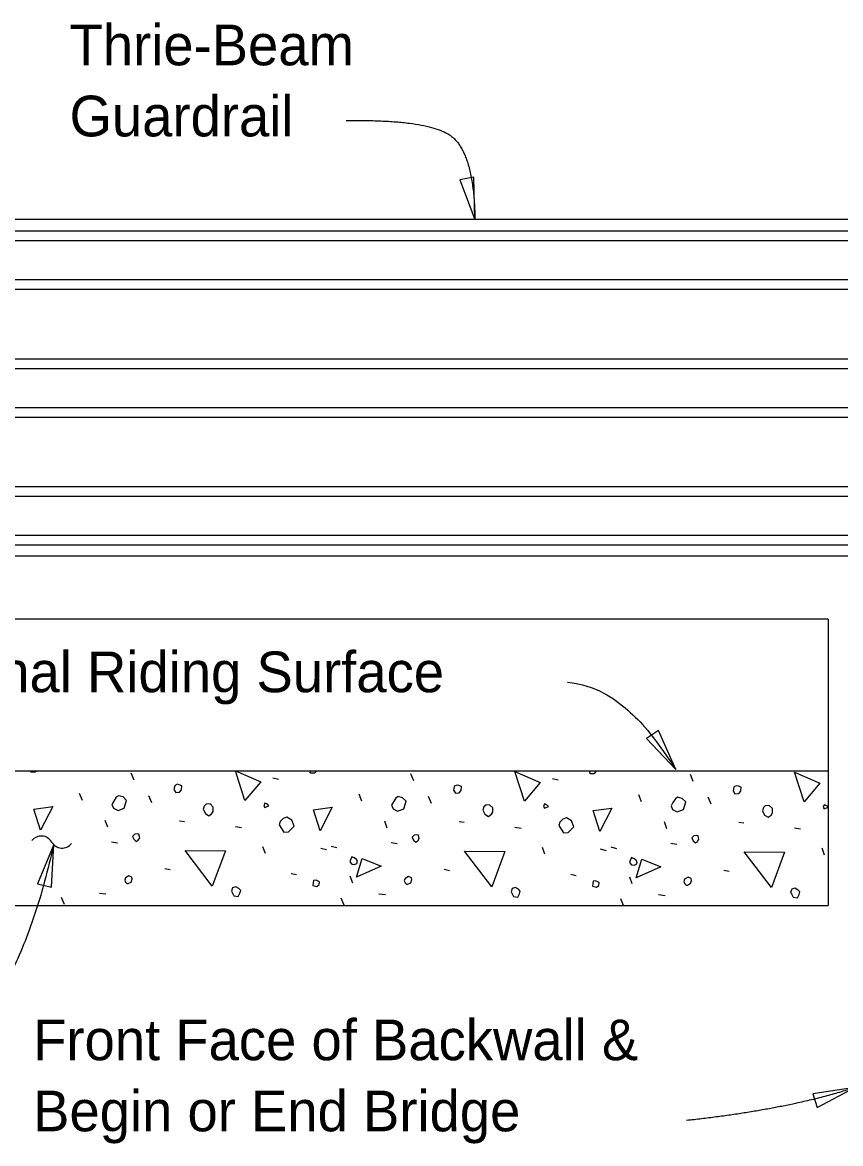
# Model space of a CAD drawing. Extents: x 21587 to 21656.3, y 56114 to 56157.2.
# Drawn here: x 21589.85 to 21593.9, y 56132.2 to 56137.76 of the extents above; entities that cross this region are included whole.
import ezdxf

# ---------------------------------------------------------------- set-up
doc = ezdxf.new("R2010")
doc.units = 0
for name, color, linetype in [('AdhocPoint_dp', 7, 'Continuous'), ('Border', 7, 'Continuous'), ('PlotBorder_dp', 7, 'Continuous'), ('SheetBorder_dp', 7, 'Continuous'), ('TextMisc', 7, 'Continuous')]:
    doc.layers.add(name, color=color, linetype=linetype)

msp = doc.modelspace()

# ---------------------------------------------------------------- linework, layer by layer
at = {"layer": 'AdhocPoint_dp'}
for p, q in [((21593.837, 56134.8009), (21587.6633, 56134.8009)), ((21593.837, 56134.8009), (21593.837, 56133.3842)), ((21587.6633, 56134.0511), (21593.837, 56134.0511)), ((21587.6633, 56133.3843), (21593.837, 56133.3843))]:
    msp.add_line(p, q, dxfattribs=at)
at = {"layer": 'Border'}
for p, q in [((21599.7592, 56136.7801), (21587.6633, 56136.7801)), ((21587.6633, 56136.7246), (21599.7592, 56136.7246)), ((21587.6633, 56136.6764), (21599.7592, 56136.6764)), ((21587.6633, 56136.4835), (21599.7592, 56136.4835)), ((21587.6633, 56136.4353), (21599.7592, 56136.4353)), ((21587.6633, 56136.0914), (21599.7592, 56136.0914)), ((21587.6633, 56136.0431), (21599.7592, 56136.0431)), ((21587.6633, 56135.8503), (21599.7592, 56135.8503)), ((21587.6633, 56135.8022), (21599.7592, 56135.8022)), ((21587.6633, 56135.4582), (21599.7592, 56135.4582)), ((21587.6633, 56135.41), (21599.7592, 56135.41)), ((21587.6633, 56135.2172), (21599.7592, 56135.2172)), ((21587.6633, 56135.169), (21599.7592, 56135.169)), ((21599.7592, 56135.1134), (21587.6633, 56135.1134))]:
    msp.add_line(p, q, dxfattribs=at)
at = {"layer": 'PlotBorder_dp'}
for points in [[(21592.0878, 56136.7801), (21592.0819, 56136.9912), (21592.0127, 56136.9775)], [(21593.0824, 56134.0576), (21592.996, 56134.2503), (21592.9373, 56134.2111)], [(21590.0017, 56133.6862), (21589.922, 56133.4906), (21589.9908, 56133.4753)], [(21593.9695, 56132.4823), (21593.7607, 56132.4504), (21593.7829, 56132.3835)]]:
    msp.add_lwpolyline(points, close=True, dxfattribs=at)
for centre, start, end in [((21589.94, 56133.6681), 30.0081, 141.7354), ((21590.0432, 56133.7277), 210.0081, 321.7354)]:
    msp.add_arc(centre, 0.0596, start, end, dxfattribs=at)
for points, degree in [([(21591.4499, 56137.2709), (21591.8868, 56137.2773), (21592.0826, 56137.086), (21592.0878, 56136.7801)], 2), ([(21592.5456, 56134.4896), (21592.6874, 56134.4753), (21592.8643, 56134.3451), (21592.9617, 56134.2379), (21593.0824, 56134.0575)], 3), ([(21590.0017, 56133.6862), (21589.743, 56132.5258), (21589.1249, 56132.603)], 2), ([(21593.9695, 56132.4824), (21593.6416, 56132.3739), (21593.1356, 56132.319)], 2)]:
    msp.add_open_spline(points, degree=degree, dxfattribs=at)
at = {"layer": 'TextMisc'}
for p, q in [((21590.3998, 56134.0043), (21590.3856, 56134.0397)), ((21591.0862, 56134.0167), (21591.1145, 56134.0096)), ((21591.7845, 56134.0008), (21591.7703, 56134.0362)), ((21593.1691, 56133.9973), (21593.155, 56134.0326)), ((21592.4709, 56134.0132), (21592.4992, 56134.0061)), ((21590.1435, 56133.9036), (21590.1293, 56133.9389)), ((21590.4875, 56133.8918), (21590.4734, 56133.9272)), ((21591.5281, 56133.9), (21591.514, 56133.9354)), ((21591.8722, 56133.8883), (21591.8581, 56133.9237)), ((21592.9128, 56133.8965), (21592.8987, 56133.9319)), ((21593.2569, 56133.8848), (21593.2428, 56133.9201)), ((21590.269, 56133.771), (21590.2566, 56133.8046)), ((21590.6254, 56133.8034), (21590.6502, 56133.7999)), ((21591.6536, 56133.7675), (21591.6413, 56133.801)), ((21592.0101, 56133.7999), (21592.0349, 56133.7964)), ((21593.0383, 56133.7639), (21593.026, 56133.7975)), ((21593.3948, 56133.7964), (21593.4195, 56133.7928)), ((21590.9012, 56133.7752), (21590.9313, 56133.7699)), ((21592.2859, 56133.7716), (21592.3159, 56133.7663)), ((21593.6706, 56133.7681), (21593.7006, 56133.7628)), ((21590.2878, 56133.6991), (21590.3178, 56133.6938)), ((21591.6725, 56133.6956), (21591.7025, 56133.6903)), ((21593.0571, 56133.6921), (21593.0872, 56133.6868)), ((21591.0497, 56133.6408), (21591.0373, 56133.6744)), ((21591.3237, 56133.6673), (21591.352, 56133.6603)), ((21591.3761, 56133.6773), (21591.4044, 56133.6702)), ((21592.4344, 56133.6373), (21592.422, 56133.6709)), ((21592.7084, 56133.6638), (21592.7367, 56133.6567)), ((21592.7608, 56133.6738), (21592.7891, 56133.6667)), ((21593.8191, 56133.6337), (21593.8067, 56133.6673)), ((21590.5512, 56133.5666), (21590.5777, 56133.5613)), ((21591.177, 56133.5418), (21591.2035, 56133.5365)), ((21591.4822, 56133.4947), (21591.4698, 56133.5283)), ((21591.9359, 56133.563), (21591.9624, 56133.5577)), ((21592.5617, 56133.5383), (21592.5882, 56133.533)), ((21592.8669, 56133.4912), (21592.8545, 56133.5248)), ((21593.3205, 56133.5595), (21593.3471, 56133.5542)), ((21590.0551, 56133.3886), (21590.0409, 56133.424)), ((21590.2277, 56133.4446), (21590.2595, 56133.4411)), ((21591.4397, 56133.3851), (21591.4256, 56133.4205)), ((21591.6124, 56133.4411), (21591.6442, 56133.4375)), ((21592.8233, 56133.3843), (21592.8103, 56133.4169)), ((21592.997, 56133.4375), (21593.0289, 56133.434))]:
    msp.add_line(p, q, dxfattribs=at)
for points in [[(21589.8864, 56134.0509), (21589.8889, 56134.045), (21589.8854, 56134.0485)], [(21589.8889, 56134.045), (21589.9101, 56134.045), (21589.9161, 56134.0509)], [(21590.9489, 56133.9042), (21590.9012, 56134.0509), (21591.0267, 56133.9961), (21590.9489, 56133.9042)], [(21591.2695, 56134.0509), (21591.2736, 56134.0415), (21591.27, 56134.045)], [(21591.2736, 56134.0415), (21591.2948, 56134.0415), (21591.3043, 56134.0509)], [(21592.3336, 56133.9007), (21592.2859, 56134.0474), (21592.4114, 56133.9926), (21592.3336, 56133.9007)], [(21592.6533, 56134.0509), (21592.653, 56134.0503), (21592.6583, 56134.0379), (21592.6547, 56134.0415)], [(21592.6583, 56134.0379), (21592.6795, 56134.0379), (21592.6901, 56134.0485), (21592.6894, 56134.0509)], [(21593.7183, 56133.8971), (21593.6706, 56134.0439), (21593.7961, 56133.9891), (21593.7183, 56133.8971)], [(21590.5971, 56133.959), (21590.606, 56133.9431), (21590.6254, 56133.9449), (21590.6343, 56133.9572), (21590.636, 56133.9767), (21590.6237, 56133.982), (21590.6148, 56133.9838), (21590.6042, 56133.9802), (21590.6007, 56133.9767), (21590.5971, 56133.959)], [(21591.9818, 56133.9555), (21591.9907, 56133.9396), (21592.0101, 56133.9413), (21592.0189, 56133.9537), (21592.0207, 56133.9731), (21592.0083, 56133.9785), (21591.9995, 56133.9802), (21591.9889, 56133.9767), (21591.9854, 56133.9731), (21591.9818, 56133.9555)], [(21593.3665, 56133.9519), (21593.3753, 56133.936), (21593.3948, 56133.9378), (21593.4036, 56133.9502), (21593.4054, 56133.9696), (21593.393, 56133.9749), (21593.3842, 56133.9767), (21593.3736, 56133.9731), (21593.37, 56133.9696), (21593.3665, 56133.9519)], [(21590.2973, 56133.8665), (21590.3202, 56133.8541), (21590.3503, 56133.8665), (21590.3627, 56133.9036), (21590.345, 56133.9213), (21590.322, 56133.9266), (21590.3114, 56133.9195), (21590.299, 56133.9), (21590.2902, 56133.8841), (21590.2973, 56133.8665)], [(21591.6819, 56133.8629), (21591.7049, 56133.8505), (21591.735, 56133.8629), (21591.7473, 56133.9), (21591.7297, 56133.9177), (21591.7067, 56133.923), (21591.6961, 56133.916), (21591.6837, 56133.8965), (21591.6749, 56133.8806), (21591.6819, 56133.8629)], [(21593.0666, 56133.8594), (21593.0896, 56133.847), (21593.1196, 56133.8594), (21593.132, 56133.8965), (21593.1143, 56133.9142), (21593.0914, 56133.9195), (21593.0808, 56133.9124), (21593.0684, 56133.893), (21593.0595, 56133.8771), (21593.0666, 56133.8594)], [(21589.9366, 56133.7569), (21589.903, 56133.8612), (21589.9967, 56133.8735), (21589.9366, 56133.7569)], [(21590.7421, 56133.86), (21590.7527, 56133.8388), (21590.7704, 56133.8282), (21590.7845, 56133.8388), (21590.7916, 56133.8494), (21590.7916, 56133.8706), (21590.7757, 56133.8865), (21590.7562, 56133.8848), (21590.7474, 56133.8759), (21590.7421, 56133.86)], [(21591.0479, 56133.8689), (21591.0674, 56133.8777), (21591.0603, 56133.8848), (21591.0479, 56133.8901), (21591.0426, 56133.8777), (21591.0479, 56133.8689)], [(21591.3213, 56133.7533), (21591.2877, 56133.8576), (21591.3814, 56133.87), (21591.3213, 56133.7533)], [(21592.1268, 56133.8565), (21592.1374, 56133.8353), (21592.1551, 56133.8247), (21592.1692, 56133.8353), (21592.1763, 56133.8459), (21592.1763, 56133.8671), (21592.1604, 56133.883), (21592.1409, 56133.8812), (21592.1321, 56133.8724), (21592.1268, 56133.8565)], [(21592.4326, 56133.8653), (21592.4521, 56133.8742), (21592.445, 56133.8812), (21592.4326, 56133.8865), (21592.4273, 56133.8742), (21592.4326, 56133.8653)], [(21592.706, 56133.7498), (21592.6724, 56133.8541), (21592.7661, 56133.8665), (21592.706, 56133.7498)], [(21593.5115, 56133.8529), (21593.5221, 56133.8317), (21593.5397, 56133.8211), (21593.5539, 56133.8317), (21593.561, 56133.8423), (21593.561, 56133.8635), (21593.545, 56133.8795), (21593.5256, 56133.8777), (21593.5168, 56133.8689), (21593.5115, 56133.8529)], [(21593.8173, 56133.8618), (21593.8367, 56133.8706), (21593.8297, 56133.8777), (21593.8173, 56133.883), (21593.812, 56133.8706), (21593.8173, 56133.8618)], [(21591.1186, 56133.784), (21591.1416, 56133.7469), (21591.1646, 56133.7486), (21591.1734, 56133.7575), (21591.1929, 56133.7769), (21591.1805, 56133.807), (21591.1558, 56133.8211), (21591.1381, 56133.814), (21591.1239, 56133.7999), (21591.1186, 56133.784)], [(21592.5033, 56133.7805), (21592.5263, 56133.7433), (21592.5493, 56133.7451), (21592.5581, 56133.7539), (21592.5776, 56133.7734), (21592.5652, 56133.8034), (21592.5404, 56133.8176), (21592.5228, 56133.8105), (21592.5086, 56133.7964), (21592.5033, 56133.7805)], [(21590.3992, 56133.7115), (21590.4098, 56133.7009), (21590.4204, 56133.708), (21590.4274, 56133.7186), (21590.4239, 56133.7363), (21590.4151, 56133.738), (21590.4027, 56133.7363), (21590.3921, 56133.7257), (21590.3992, 56133.7115)], [(21591.7838, 56133.708), (21591.7944, 56133.6974), (21591.8051, 56133.7044), (21591.8121, 56133.7151), (21591.8086, 56133.7327), (21591.7997, 56133.7345), (21591.7874, 56133.7327), (21591.7768, 56133.7221), (21591.7838, 56133.708)], [(21593.1685, 56133.7044), (21593.1791, 56133.6938), (21593.1897, 56133.7009), (21593.1968, 56133.7115), (21593.1933, 56133.7292), (21593.1844, 56133.731), (21593.172, 56133.7292), (21593.1614, 56133.7186), (21593.1685, 56133.7044)], [(21590.7863, 56133.4799), (21590.652, 56133.6567), (21590.8517, 56133.655), (21590.7863, 56133.4799)], [(21592.171, 56133.4764), (21592.0366, 56133.6532), (21592.2364, 56133.6514), (21592.171, 56133.4764)], [(21593.5557, 56133.4729), (21593.4213, 56133.6496), (21593.6211, 56133.6479), (21593.5557, 56133.4729)], [(21591.4786, 56133.5889), (21591.491, 56133.5871), (21591.5034, 56133.5925), (21591.5069, 56133.6031), (21591.5016, 56133.6119), (21591.491, 56133.619), (21591.4786, 56133.6243), (21591.4716, 56133.6101), (21591.468, 56133.5995), (21591.4786, 56133.5889)], [(21591.501, 56133.5241), (21591.5293, 56133.6161), (21591.623, 56133.5789), (21591.501, 56133.5241)], [(21592.8633, 56133.5854), (21592.8757, 56133.5836), (21592.8881, 56133.5889), (21592.8916, 56133.5995), (21592.8863, 56133.6084), (21592.8757, 56133.6154), (21592.8633, 56133.6207), (21592.8562, 56133.6066), (21592.8527, 56133.596), (21592.8633, 56133.5854)], [(21592.8857, 56133.5206), (21592.914, 56133.6125), (21593.0076, 56133.5754), (21592.8857, 56133.5206)], [(21590.3638, 56133.4923), (21590.3709, 56133.4923), (21590.385, 56133.4994), (21590.3903, 56133.5153), (21590.3886, 56133.5241), (21590.3744, 56133.5312), (21590.3567, 56133.5206), (21590.3532, 56133.51), (21590.3567, 56133.4994), (21590.3638, 56133.4923)], [(21591.7485, 56133.4888), (21591.7556, 56133.4888), (21591.7697, 56133.4959), (21591.775, 56133.5118), (21591.7732, 56133.5206), (21591.7591, 56133.5277), (21591.7414, 56133.5171), (21591.7379, 56133.5065), (21591.7414, 56133.4959), (21591.7485, 56133.4888)], [(21593.1332, 56133.4852), (21593.1402, 56133.4852), (21593.1544, 56133.4923), (21593.1597, 56133.5082), (21593.1579, 56133.5171), (21593.1438, 56133.5241), (21593.1261, 56133.5135), (21593.1226, 56133.5029), (21593.1261, 56133.4923), (21593.1332, 56133.4852)], [(21590.8853, 56133.4481), (21590.8941, 56133.4322), (21590.9153, 56133.4287), (21590.9242, 56133.4446), (21590.9277, 56133.4587), (21590.9189, 56133.4676), (21590.903, 56133.4764), (21590.8871, 56133.4711), (21590.8818, 56133.4552), (21590.8853, 56133.4481)], [(21591.2848, 56133.4835), (21591.3043, 56133.4782), (21591.3166, 56133.487), (21591.3184, 56133.4994), (21591.3149, 56133.5029), (21591.3007, 56133.51), (21591.2883, 56133.5082), (21591.2866, 56133.4959), (21591.2848, 56133.4835)], [(21592.27, 56133.4446), (21592.2788, 56133.4287), (21592.3, 56133.4251), (21592.3089, 56133.4411), (21592.3124, 56133.4552), (21592.3036, 56133.464), (21592.2877, 56133.4729), (21592.2717, 56133.4676), (21592.2664, 56133.4517), (21592.27, 56133.4446)], [(21592.6695, 56133.4799), (21592.6889, 56133.4746), (21592.7013, 56133.4835), (21592.7031, 56133.4959), (21592.6995, 56133.4994), (21592.6854, 56133.5065), (21592.673, 56133.5047), (21592.6713, 56133.4923), (21592.6695, 56133.4799)], [(21593.6546, 56133.4411), (21593.6635, 56133.4251), (21593.6847, 56133.4216), (21593.6935, 56133.4375), (21593.6971, 56133.4517), (21593.6882, 56133.4605), (21593.6723, 56133.4693), (21593.6564, 56133.464), (21593.6511, 56133.4481), (21593.6546, 56133.4411)]]:
    msp.add_lwpolyline(points, dxfattribs=at)

# ---------------------------------------------------------------- texts
at = {"layer": 'PlotBorder_dp'}
for s, p in [('Thrie-Beam ', (21590.0802, 56137.5444)), ('Guardrail', (21590.0802, 56137.1924)), ('Front Face of Backwall &', (21589.8998, 56132.6176)), ('Begin or End Bridge', (21589.8998, 56132.2656))]:
    msp.add_text(s, height=0.2016, dxfattribs=at).set_placement(p)
at = {"layer": 'SheetBorder_dp'}
msp.add_text('Final Riding Surface', height=0.2016, dxfattribs=at).set_placement((21589.5074, 56134.4399))

doc.saveas('drawing.dxf')
